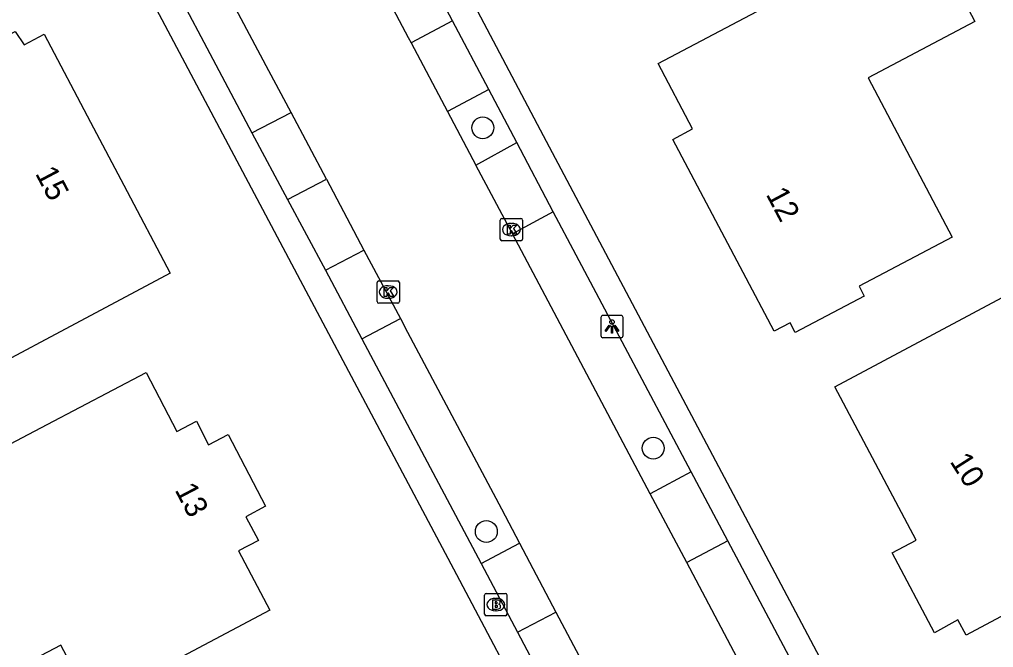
# Model space of a CAD drawing. Extents: x 160457 to 162082, y 388340 to 389736.
# Drawn here: x 160653.48 to 160697.07, y 389128.73 to 389156.82 of the extents above; entities that cross this region are included whole.
import ezdxf

# ---------------------------------------------------------------- set-up
doc = ezdxf.new("R2010")
doc.units = 0
for name, color, linetype in [('IMGEO_Boom', 7, 'Continuous'), ('IMGEO_Brandkraan', 7, 'Continuous'), ('IMGEO_Kolk', 7, 'Continuous'), ('IMGEO_Lichtpunt', 7, 'Continuous'), ('IMGEO_Pand', 7, 'Continuous'), ('IMGEO_Pand_nummerreeks', 7, 'Continuous'), ('IMGEO_Rijbaan_lokaal_gesloten', 7, 'Continuous'), ('IMGEO_Voetpad_open', 7, 'Continuous')]:
    doc.layers.add(name, color=color, linetype=linetype)

msp = doc.modelspace()

# ---------------------------------------------------------------- linework, layer by layer
at = {"layer": 'IMGEO_Boom'}
for centre in [(160674.213, 389151.975), (160681.842, 389137.648), (160674.373, 389133.918)]:
    msp.add_circle(centre, 0.489, dxfattribs=at)
at = {"layer": 'IMGEO_Brandkraan'}
for p, q in [((160674.296, 389130.226), (160674.296, 389131.078)), ((160674.371, 389131.152), (160675.223, 389131.152)), ((160674.784, 389130.932), (160674.809, 389130.932)), ((160675.297, 389131.078), (160675.297, 389130.226)), ((160675.223, 389130.152), (160674.371, 389130.152)), ((160674.807, 389130.372), (160674.782, 389130.372))]:
    msp.add_line(p, q, dxfattribs=at)
for points in [[(160674.296, 389130.226), (160674.296, 389131.078)], [(160674.371, 389131.152), (160675.223, 389131.152)], [(160675.297, 389131.078), (160675.297, 389130.226)], [(160674.644, 389130.852), (160674.644, 389130.452), (160674.857, 389130.452)], [(160674.875, 389130.852), (160674.644, 389130.852)], [(160674.823, 389130.771), (160674.769, 389130.771), (160674.769, 389130.695)], [(160674.769, 389130.695), (160674.822, 389130.695)], [(160674.831, 389130.619), (160674.769, 389130.619), (160674.769, 389130.538)], [(160674.769, 389130.538), (160674.831, 389130.538)], [(160675.223, 389130.152), (160674.371, 389130.152)]]:
    msp.add_lwpolyline(points, dxfattribs=at)
for centre, radius, start, end in [((160674.373, 389131.076), 0.0765, 91.552, 178.448), ((160674.373, 389131.076), 0.0765, 91.552, 178.448), ((160675.221, 389131.076), 0.0765, 1.552, 88.448), ((160675.221, 389131.076), 0.0765, 1.552, 88.448), ((160674.824, 389130.733), 0.0379, 267.8285, 90.9355), ((160674.832, 389130.578), 0.0404, 269.8759, 90.5077), ((160674.863, 389130.703), 0.251, 268.6676, 293.5347), ((160674.879, 389130.707), 0.145, 59.4692, 91.5367), ((160674.904, 389130.754), 0.0922, 285.5137, 58.1501), ((160674.909, 389130.562), 0.105, 301.3115, 78.989), ((160674.373, 389130.228), 0.0765, 181.552, 268.448), ((160674.373, 389130.228), 0.0765, 181.552, 268.448), ((160675.221, 389130.228), 0.0765, 271.552, 358.448), ((160675.221, 389130.228), 0.0765, 271.552, 358.448)]:
    msp.add_arc(centre, radius, start, end, dxfattribs=at)
for centre, major_axis, ratio, start_param, end_param in [((160674.783, 389130.652), (-0.387, 0.002), 0.722429, 4.712389, 7.853982), ((160674.808, 389130.652), (-0.39, 0.002), 0.717154, 1.570796, 4.712389)]:
    msp.add_ellipse(centre, major_axis=major_axis, ratio=ratio, start_param=start_param, end_param=end_param, dxfattribs=at)
at = {"layer": 'IMGEO_Kolk'}
for p, q in [((160675.068, 389147.922), (160675.92, 389147.922)), ((160674.993, 389146.996), (160674.993, 389147.848)), ((160675.481, 389147.702), (160675.506, 389147.702)), ((160675.994, 389147.848), (160675.994, 389146.996)), ((160675.504, 389147.142), (160675.479, 389147.142)), ((160675.92, 389146.922), (160675.068, 389146.922)), ((160669.48, 389144.204), (160669.48, 389145.056)), ((160669.555, 389145.13), (160670.407, 389145.13)), ((160669.968, 389144.91), (160669.993, 389144.91)), ((160670.481, 389145.056), (160670.481, 389144.204)), ((160670.407, 389144.13), (160669.555, 389144.13)), ((160669.991, 389144.35), (160669.966, 389144.35))]:
    msp.add_line(p, q, dxfattribs=at)
for points in [[(160675.068, 389147.922), (160675.92, 389147.922)], [(160674.993, 389146.996), (160674.993, 389147.848)], [(160675.314, 389147.622), (160675.437, 389147.622), (160675.437, 389147.471), (160675.567, 389147.622), (160675.731, 389147.622), (160675.585, 389147.471), (160675.738, 389147.222), (160675.586, 389147.222), (160675.501, 389147.386), (160675.437, 389147.319), (160675.437, 389147.222), (160675.314, 389147.222), (160675.314, 389147.622)], [(160675.994, 389147.848), (160675.994, 389146.996)], [(160675.92, 389146.922), (160675.068, 389146.922)], [(160669.48, 389144.204), (160669.48, 389145.056)], [(160669.555, 389145.13), (160670.407, 389145.13)], [(160670.481, 389145.056), (160670.481, 389144.204)], [(160669.801, 389144.83), (160669.924, 389144.83), (160669.924, 389144.679), (160670.054, 389144.83), (160670.218, 389144.83), (160670.072, 389144.679), (160670.225, 389144.43), (160670.073, 389144.43), (160669.988, 389144.594), (160669.924, 389144.527), (160669.924, 389144.43), (160669.801, 389144.43), (160669.801, 389144.83)], [(160670.407, 389144.13), (160669.555, 389144.13)]]:
    msp.add_lwpolyline(points, dxfattribs=at)
for centre, start, end in [((160675.07, 389147.846), 91.552, 178.448), ((160675.07, 389147.846), 91.552, 178.448), ((160675.918, 389147.846), 1.552, 88.448), ((160675.918, 389147.846), 1.552, 88.448), ((160675.07, 389146.998), 181.552, 268.448), ((160675.07, 389146.998), 181.552, 268.448), ((160675.918, 389146.998), 271.552, 358.448), ((160675.918, 389146.998), 271.552, 358.448), ((160669.557, 389145.054), 91.552, 178.448), ((160669.557, 389145.054), 91.552, 178.448), ((160670.405, 389145.054), 1.552, 88.448), ((160670.405, 389145.054), 1.552, 88.448), ((160669.557, 389144.206), 181.552, 268.448), ((160669.557, 389144.206), 181.552, 268.448), ((160670.405, 389144.206), 271.552, 358.448), ((160670.405, 389144.206), 271.552, 358.448)]:
    msp.add_arc(centre, 0.0765, start, end, dxfattribs=at)
for centre, major_axis, ratio, start_param, end_param in [((160675.48, 389147.422), (-0.387, 0.002), 0.722429, 4.712389, 7.853982), ((160675.505, 389147.422), (-0.39, 0.002), 0.717154, 1.570796, 4.712389), ((160669.967, 389144.63), (-0.387, 0.002), 0.722429, 4.712389, 7.853982), ((160669.992, 389144.63), (-0.39, 0.002), 0.717154, 1.570796, 4.712389)]:
    msp.add_ellipse(centre, major_axis=major_axis, ratio=ratio, start_param=start_param, end_param=end_param, dxfattribs=at)
at = {"layer": 'IMGEO_Lichtpunt'}
for p, q in [((160680.4, 389143.586), (160679.592, 389143.586)), ((160680.4, 389143.586), (160679.592, 389143.586)), ((160679.498, 389143.491), (160679.498, 389142.684)), ((160679.498, 389143.491), (160679.498, 389142.684)), ((160680.494, 389142.684), (160680.494, 389143.491)), ((160680.494, 389142.684), (160680.494, 389143.491)), ((160679.592, 389142.59), (160680.4, 389142.59)), ((160679.592, 389142.59), (160680.4, 389142.59))]:
    msp.add_line(p, q, dxfattribs=at)
for points in [[(160679.872, 389143.155), (160679.911, 389143.127), (160679.723, 389142.865), (160679.685, 389142.892), (160679.872, 389143.155)], [(160679.974, 389143.107), (160680.021, 389143.107), (160680.021, 389142.785), (160679.974, 389142.785), (160679.974, 389143.107)], [(160680.084, 389143.127), (160680.122, 389143.154), (160680.309, 389142.892), (160680.27, 389142.864), (160680.084, 389143.127)]]:
    msp.add_lwpolyline(points, dxfattribs=at)
msp.add_circle((160679.997, 389143.289), 0.0994, dxfattribs=at)
for centre, start, end in [((160679.592, 389143.491), 90, 180), ((160679.592, 389143.491), 90, 180), ((160680.4, 389143.491), 0, 90), ((160680.4, 389143.491), 0, 90), ((160679.592, 389142.684), 180, 270), ((160679.592, 389142.684), 180, 270), ((160680.4, 389142.684), 270, 0), ((160680.4, 389142.684), 270, 360)]:
    msp.add_arc(centre, 0.0946, start, end, dxfattribs=at)
at = {"layer": 'IMGEO_Pand'}
for points in [[(160695.216, 389147.083), (160691.054, 389144.889), (160691.288, 389144.446), (160688.198, 389142.817), (160687.964, 389143.259), (160687.256, 389142.886), (160685.872, 389145.498), (160684.088, 389148.864), (160682.715, 389151.456), (160683.6, 389151.923), (160682.06, 389154.845), (160686.484, 389157.177), (160693.933, 389161.104), (160696.239, 389156.731), (160691.458, 389154.21), (160695.216, 389147.083)], [(160647.961, 389138.948), (160644.433, 389145.568), (160645.48, 389146.134), (160643.924, 389149.013), (160647.763, 389151.088), (160647.48, 389151.611), (160648.248, 389152.026), (160647.918, 389152.637), (160650.849, 389154.187), (160650.515, 389154.818), (160653.283, 389156.282), (160653.691, 389155.69), (160654.579, 389156.16), (160656.661, 389152.224), (160658.154, 389149.402), (160660.229, 389145.48), (160647.961, 389138.948)], [(160705.133, 389138.268), (160702.125, 389136.663), (160702.379, 389136.186), (160702.953, 389136.107), (160703.733, 389134.607), (160703.478, 389134.086), (160703.779, 389133.521), (160703.207, 389133.216), (160703.146, 389132.651), (160701.673, 389131.864), (160701.16, 389132.124), (160695.849, 389129.29), (160695.482, 389129.968), (160694.426, 389129.396), (160692.533, 389132.965), (160693.604, 389133.532), (160689.972, 389140.389), (160694.384, 389142.743), (160697.905, 389144.622), (160698.987, 389142.595), (160703.218, 389144.852), (160705.728, 389140.15), (160705.133, 389138.268)], [(160660.27, 389128.061), (160656.728, 389126.188), (160655.325, 389128.842), (160652.662, 389127.434), (160649.853, 389132.76), (160652.51, 389134.163), (160651.112, 389136.811), (160654.723, 389138.709), (160659.148, 389141.035), (160660.519, 389138.399), (160661.395, 389138.854), (160661.941, 389137.804), (160662.817, 389138.259), (160664.495, 389135.049), (160663.61, 389134.581), (160664.172, 389133.52), (160663.287, 389133.052), (160664.69, 389130.398), (160660.27, 389128.061)]]:
    msp.add_lwpolyline(points, dxfattribs=at)
at = {"layer": 'IMGEO_Rijbaan_lokaal_gesloten'}
for points in [[(160663.31, 389170.36), (160664.462, 389168.152), (160670.877, 389156.01), (160671.006, 389155.768)], [(160665.631, 389152.662), (160664.641, 389154.526), (160658.204, 389166.618)], [(160671.006, 389155.768), (160672.636, 389152.697)], [(160672.636, 389152.697), (160673.905, 389150.307)], [(160667.215, 389149.678), (160665.631, 389152.662)], [(160675.538, 389147.232), (160673.905, 389150.307)], [(160667.215, 389149.678), (160668.897, 389146.509)], [(160681.712, 389135.604), (160678.873, 389140.95), (160675.538, 389147.232)], [(160668.897, 389146.509), (160670.526, 389143.441)], [(160670.526, 389143.441), (160670.844, 389142.842), (160675.044, 389134.929), (160675.851, 389133.404)], [(160683.343, 389132.534), (160681.712, 389135.604)], [(160675.851, 389133.404), (160677.483, 389130.318)], [(160689.524, 389120.887), (160685.454, 389128.559), (160683.343, 389132.534)], [(160677.483, 389130.318), (160681.399, 389122.914), (160684.135, 389117.759)]]:
    msp.add_lwpolyline(points, dxfattribs=at)
at = {"layer": 'IMGEO_Voetpad_open'}
for points in [[(160666.197, 389171.948), (160666.685, 389171.014), (160676.789, 389151.881), (160708.027, 389092.962), (160711.74, 389086.082), (160713.992, 389081.813), (160714.548, 389080.749), (160722.246, 389065.089), (160725.803, 389057.769), (160726.725, 389055.856)], [(160672.858, 389156.76), (160666.471, 389168.85), (160665.161, 389171.314)], [(160656.529, 389165.68), (160658.792, 389161.365), (160663.88, 389151.748)], [(160715.497, 389049.443), (160715.59, 389049.493), (160705.696, 389069.922), (160703.712, 389073.937), (160701.581, 389078.055), (160687.433, 389104.792), (160673.051, 389131.978), (160665.928, 389145.4), (160655.489, 389165.053), (160655.393, 389165.23)], [(160672.858, 389156.76), (160671.006, 389155.768)], [(160674.482, 389153.685), (160672.858, 389156.76)], [(160674.482, 389153.685), (160672.636, 389152.697)], [(160675.731, 389151.322), (160674.482, 389153.685)], [(160663.88, 389151.748), (160665.631, 389152.662)], [(160663.88, 389151.748), (160665.468, 389148.764)], [(160673.905, 389150.307), (160675.731, 389151.322)], [(160677.365, 389148.219), (160675.731, 389151.322)], [(160665.468, 389148.764), (160667.215, 389149.678)], [(160665.468, 389148.764), (160667.177, 389145.606)], [(160677.365, 389148.219), (160675.538, 389147.232)], [(160683.547, 389136.589), (160677.365, 389148.219)], [(160667.177, 389145.606), (160668.897, 389146.509)], [(160667.177, 389145.606), (160668.807, 389142.541)], [(160668.807, 389142.541), (160670.526, 389143.441)], [(160668.807, 389142.541), (160674.138, 389132.488)], [(160683.547, 389136.589), (160681.712, 389135.604)], [(160685.179, 389133.511), (160683.547, 389136.589)], [(160674.138, 389132.488), (160675.851, 389133.404)], [(160685.179, 389133.511), (160683.343, 389132.534)], [(160691.351, 389121.867), (160685.179, 389133.511)], [(160674.138, 389132.488), (160675.769, 389129.425)], [(160675.769, 389129.425), (160677.483, 389130.318)], [(160675.769, 389129.425), (160682.426, 389116.839)]]:
    msp.add_lwpolyline(points, dxfattribs=at)

# ---------------------------------------------------------------- texts
at = {"layer": 'IMGEO_Pand_nummerreeks'}
for s, rotation, p in [('15', 297.88, (160654.161, 389149.936)), ('12', 297.9178, (160686.867, 389149.003)), ('10', 302.561, (160695.091, 389137.054)), ('13', 297.5979, (160660.409, 389135.787))]:
    msp.add_text(s, height=1, rotation=rotation, dxfattribs=at).set_placement(p)

doc.saveas('drawing.dxf')
